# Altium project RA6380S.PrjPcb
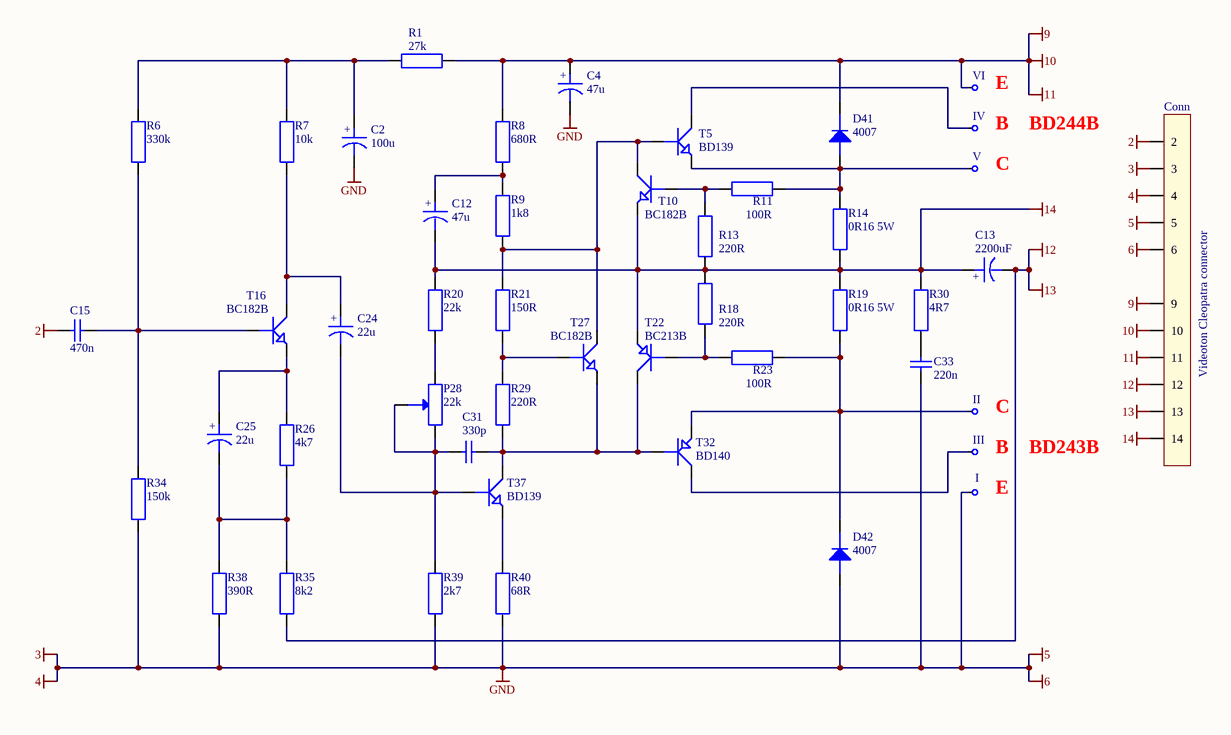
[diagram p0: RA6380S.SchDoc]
1 sheet, 47 parts. Net scope: global (net labels, ports and power ports of the same name join across sheets).
Board file: RA6380S.PcbDoc

## Sheet RA6380S.SchDoc
size A4

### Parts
C2  100u  [038RSU]
C4  47u  [038RSU]
C12  47u  [038RSU]
C13  2200uF  [2200uF 40V axial]
C15  470n  [C2334 400V]
C24  22u  [MAL203831229E3]
C25  22u  [MAL203831229E3]
C31  330p  [C2441]
C33  220n  [C2334 400V]
Conn  Videoton Cleopatra connector  [Videoton Cleopatra connector]
D41  4007  [DO-41]
D42  4007  [DO-41]
I  1pin  [1pin 1.4x3]  (value not drawn)
II  1pin  [1pin 1.4x3]  (value not drawn)
III  1pin  [1pin 1.4x3]  (value not drawn)
IV  1pin  [1pin 1.4x3]  (value not drawn)
P28  22k  [TP095]
R1  27k  [MF0207]
R6  330k  [MF0207]
R7  10k  [MF0207]
R8  680R  [MF0207]
R9  1k8  [MF0207]
R11  100R  [MF0207]
R13  220R  [MF0207]
R14  0R16 5W  [KNP5WS]
R18  220R  [MF0207]
R19  0R16 5W  [KNP5WS]
R20  22k  [MF0207]
R21  150R  [MF0207]
R23  100R  [MF0207]
R26  4k7  [MF0207]
R29  220R  [MF0207]
R30  4R7  [MOR03]
R34  150k  [MF0207]
R35  8k2  [MF0207]
R38  390R  [MF0207]
R39  2k7  [MF0207]
R40  68R  [MF0207]
T5  BD139  [BD139]
T10  BC182B  [BC557]
T16  BC182B  [BC547]
T22  BC213B  [BC557]
T27  BC182B  [BC557]
T32  BD140  [BD139]
T37  BD139  [BD139]
V  1pin  [1pin 1.4x3]  (value not drawn)
VI  1pin  [1pin 1.4x3]  (value not drawn)

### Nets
2: C15.1 Conn.2
3: C2.2 C4.2 C33.1 Conn.3 Conn.4 Conn.5 Conn.6 D42.A I.1 R34.1 R38.1 R39.1 R40.1  [also labelled 4, 5, 6, GND]
10: C4.1 Conn.9 Conn.10 Conn.11 D41.K R1.1 R8.2 VI.1  [also labelled 11, 9]
12: C13.2 Conn.12 Conn.13 R35.1  [also labelled 13]
14: C12.2 C13.1 Conn.14 R13.1 R14.2 R18.2 R19.1 R20.2 R30.1 T10.E T22.E
NetC2_1: C2.1 R1.2 R6.2 R7.2
NetC12_1: C12.1 R8.1 R9.2
NetC15_2: C15.2 R6.1 R34.2 T16.B
NetC24_1: C24.1 R7.1 T16.C
NetC24_2: C24.2 C31.1 P28.2 P28.W R39.2 T37.B
NetC25_1: C25.1 R26.2 T16.E
NetC25_2: C25.2 R26.1 R35.2 R38.2
NetC31_2: C31.2 R29.1 T22.C T27.E T32.B T37.C
NetC33_2: C33.2 R30.2
NetD41_A: D41.A R11.1 R14.1 T5.E V.1
NetD42_K: D42.K II.1 R19.2 R23.1 T32.E
NetIII_1: III.1 T32.C
NetIV_1: IV.1 T5.C
NetP28_1: P28.1 R20.1
NetR9_1: R9.1 R21.2 T5.B T10.C T27.C
NetR11_2: R11.2 R13.2 T10.B
NetR18_1: R18.1 R23.2 T22.B
NetR21_1: R21.1 R29.2 T27.B
NetR40_2: R40.2 T37.E

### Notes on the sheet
- (near VI) E
- C
- B
- BD244B
- (near II) C
- BD243B
- E

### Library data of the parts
C2 C4 C12 C13 C24 C25 = CAP POL
C15 C31 C33 = CAP
D41 D42 = Dioda
P28 = RES POT2
R1 R6-R9 R11 R13 R14 R18-R21 R23 R26 R29 R30 R34 R35 R38-R40 = RES_THT
T5 T10 T16 T27 T37 = NPN
T22 T32 = PNP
